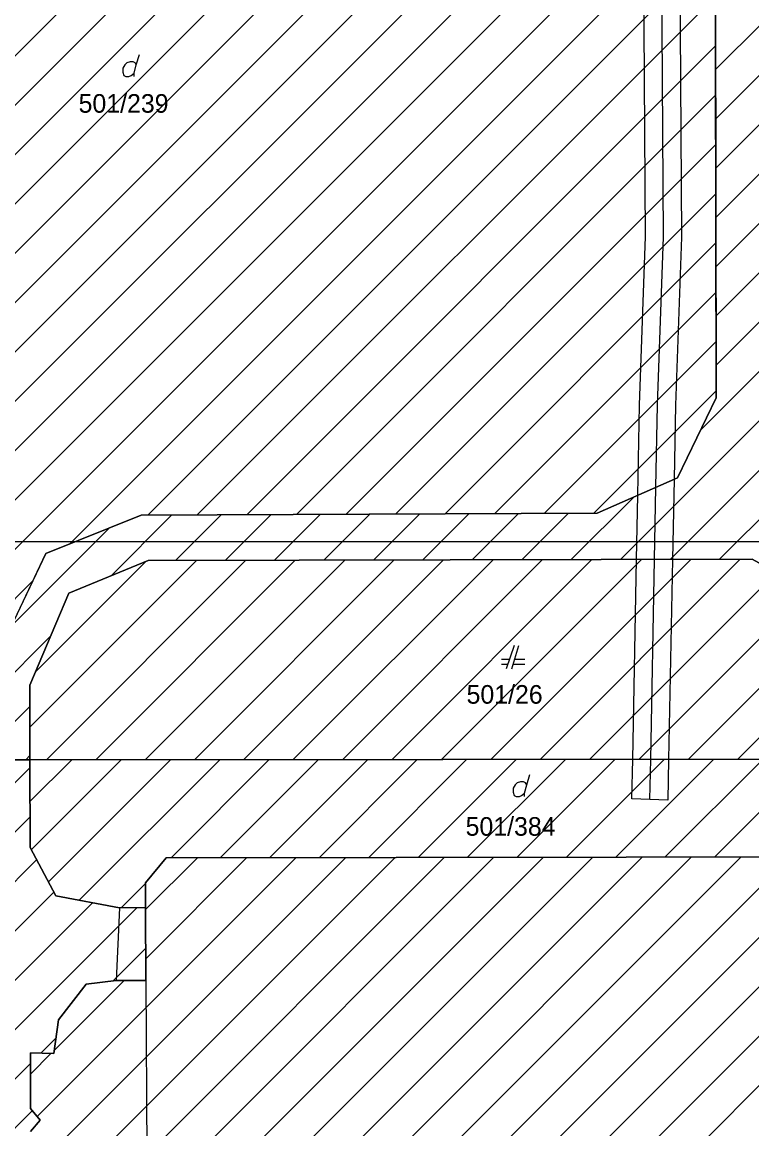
# Model space of a CAD drawing. Extents: x -264309 to -263505, y -1242443 to -1241763.
# Drawn here: x -264073.7 to -264010.9, y -1242101 to -1242005.9 of the extents above; entities that cross this region are included whole.
import ezdxf

# ---------------------------------------------------------------- set-up
doc = ezdxf.new("R2010")
doc.units = 0
for name, color, linetype in [('KN_2019_08_16', 7, 'Continuous'), ('KN_2019_08_16_KLADPAR', 7, 'Continuous'), ('KN_2019_08_16_ZAPPAR', 7, 'Continuous'), ('RAM_NA_TLAC_10xA4_1-500', 7, 'Continuous'), ('SRAFY_PARCELY', 7, 'Continuous')]:
    doc.layers.add(name, color=color, linetype=linetype)

msp = doc.modelspace()

# ---------------------------------------------------------------- linework, layer by layer
at = {"layer": 'KN_2019_08_16'}
msp.add_lwpolyline([(-264014.44, -1241960.47), (-264017.32, -1241970.61), (-264016.97, -1242024.38), (-264017.48, -1242038.84), (-264017.6, -1242045.19), (-264017.74, -1242052.08), (-264018.07, -1242069.28), (-264018.14, -1242072.77), (-264019.68, -1242072.72), (-264021.23, -1242072.66), (-264021.16, -1242069.28), (-264020.83, -1242052.09), (-264020.73, -1242046.57), (-264020.58, -1242038.83), (-264020.07, -1242024.34), (-264020.4, -1241970.09), (-264017.76, -1241960.8), (-264016.1, -1241960.64)], close=True, dxfattribs=at)
msp.add_lwpolyline([(-264019.68, -1242072.72), (-264019.61, -1242069.28), (-264019.28, -1242052.09), (-264019.16, -1242045.88), (-264019.03, -1242038.83), (-264018.52, -1242024.36), (-264018.86, -1241970.35), (-264016.1, -1241960.64)], dxfattribs=at)
at = {"layer": 'KN_2019_08_16_KLADPAR'}
for p, q in [((-264014.12, -1241964.15), (-264013.98, -1242038.21)), ((-264063.85, -1242009.58), (-264063.58, -1242008.68)), ((-264013.98, -1242038.21), (-264017.32, -1242045.06)), ((-264017.32, -1242045.06), (-264024.22, -1242048.12)), ((-264063.42, -1242048.29), (-264071.64, -1242051.59)), ((-264024.22, -1242048.12), (-264063.42, -1242048.29)), ((-264071.64, -1242051.59), (-264076.8, -1242062.43)), ((-264031.35, -1242059.5), (-264032.05, -1242061.5)), ((-264031.55, -1242061.5), (-264030.95, -1242059.5)), ((-264031.77, -1242060.7), (-264032.45, -1242060.7)), ((-264032.45, -1242061.1), (-264031.91, -1242061.1)), ((-264031.43, -1242061.1), (-264030.45, -1242061.1)), ((-264030.45, -1242060.7), (-264031.31, -1242060.7)), ((-264030.28, -1242071.47), (-264030.01, -1242070.57))]:
    msp.add_line(p, q, dxfattribs=at)
for points in [[(-264076.8, -1242062.43), (-264071.64, -1242051.59), (-264063.42, -1242048.29), (-264024.22, -1242048.12), (-264017.32, -1242045.06), (-264013.98, -1242038.21), (-264014.12, -1241964.15)], [(-264064.03, -1242010.57), (-264064.03, -1242010.3), (-264063.85, -1242009.58), (-264063.94, -1242009.4), (-264064.12, -1242009.31), (-264064.39, -1242009.31), (-264064.66, -1242009.4), (-264064.84, -1242009.58), (-264065.02, -1242009.85), (-264065.02, -1242010.21), (-264064.93, -1242010.48), (-264064.75, -1242010.57), (-264064.48, -1242010.57), (-264064.3, -1242010.48), (-264064.03, -1242010.3)], [(-263949.96, -1242070.83), (-263956.24, -1242069.24), (-263956.44, -1242060.64), (-263958.74, -1242055.68), (-263966.57, -1242052.07), (-263989.51, -1242052.11), (-263994.74, -1242054.37), (-263998.21, -1242059.87), (-263998.88, -1242069.26), (-264001.98, -1242069.27), (-264002.01, -1242061.78), (-264004.7, -1242055.47), (-264010.89, -1242052.07), (-264062.83, -1242052.18), (-264069.66, -1242054.98), (-264073.01, -1242062.91), (-264073, -1242069.31), (-264076.82, -1242069.31)], [(-264076.93, -1242111.1), (-264076.9, -1242098.2), (-264076.82, -1242069.31), (-264073, -1242069.31), (-264072.99, -1242076.85), (-264070.77, -1242081.01), (-264065.29, -1242082.03), (-264063.05, -1242082.02), (-264063.02, -1242088.27), (-264065.59, -1242088.27), (-264068.16, -1242088.59), (-264070.53, -1242091.66), (-264070.93, -1242094.55), (-264072.96, -1242094.5), (-264072.96, -1242099.3), (-264072.11, -1242100.28), (-264072.96, -1242101.25)], [(-264030.46, -1242072.46), (-264030.46, -1242072.19), (-264030.28, -1242071.47), (-264030.37, -1242071.29), (-264030.55, -1242071.2), (-264030.82, -1242071.2), (-264031.09, -1242071.29), (-264031.27, -1242071.47), (-264031.45, -1242071.74), (-264031.45, -1242072.1), (-264031.36, -1242072.37), (-264031.18, -1242072.46), (-264030.91, -1242072.46), (-264030.73, -1242072.37), (-264030.46, -1242072.19)], [(-264072.96, -1242101.25), (-264072.11, -1242100.28), (-264072.96, -1242099.3), (-264072.96, -1242094.5), (-264070.93, -1242094.55), (-264070.53, -1242091.66), (-264068.16, -1242088.59), (-264065.59, -1242088.27), (-264063.02, -1242088.27), (-264063.05, -1242082.02), (-264063.06, -1242079.88), (-264061.28, -1242077.73), (-264001.95, -1242077.64), (-264002.01, -1242080.21), (-263996.04, -1242080), (-263982.23, -1242080.21), (-263982.23, -1242081.51), (-263975.78, -1242081.51), (-263975.68, -1242093.61), (-263970.24, -1242093.63), (-263970.22, -1242106.22)]]:
    msp.add_lwpolyline(points, dxfattribs=at)
for points in [[(-264002.01, -1242061.78), (-264001.98, -1242069.27), (-264073, -1242069.31), (-264073.01, -1242062.91), (-264069.66, -1242054.98), (-264062.83, -1242052.18), (-264010.89, -1242052.07), (-264004.7, -1242055.47)], [(-264073, -1242069.31), (-264001.98, -1242069.27), (-264001.95, -1242077.64), (-264061.28, -1242077.73), (-264063.06, -1242079.88), (-264063.05, -1242082.02), (-264065.29, -1242082.03), (-264070.77, -1242081.01), (-264072.99, -1242076.85)]]:
    msp.add_lwpolyline(points, close=True, dxfattribs=at)
at = {"layer": 'KN_2019_08_16_ZAPPAR'}
for p, q in [((-264065.29, -1242082.03), (-264065.59, -1242088.27)), ((-264063.02, -1242088.27), (-264062.89, -1242112.12))]:
    msp.add_line(p, q, dxfattribs=at)
at = {"layer": 'RAM_NA_TLAC_10xA4_1-500'}
msp.add_lwpolyline([(-264210.825, -1242050.537), (-264105.825, -1242050.537), (-264000.825, -1242050.537), (-263895.825, -1242050.537), (-263790.825, -1242050.537), (-263685.825, -1242050.537), (-263685.825, -1242199.037), (-263685.825, -1242347.537), (-263790.825, -1242347.537), (-263895.825, -1242347.537), (-264000.825, -1242347.537), (-264105.825, -1242347.537), (-264210.825, -1242347.537), (-264210.825, -1242199.037)], close=True, dxfattribs=at)
at = {"layer": 'SRAFY_PARCELY'}
for p, q in [((-264101.288, -1242048.528), (-264013.095, -1241960.335)), ((-264104.076, -1242042.83), (-264022.521, -1241961.276)), ((-264102.682, -1242045.679), (-264017.809, -1241960.806)), ((-264105.469, -1242039.982), (-264027.233, -1241961.745)), ((-264099.9, -1242051.383), (-264014.117, -1241965.6)), ((-264098.588, -1242054.313), (-264014.109, -1241969.835)), ((-264097.275, -1242057.243), (-264014.101, -1241974.069)), ((-264095.962, -1242060.173), (-264014.093, -1241978.304)), ((-264094.65, -1242063.103), (-264014.085, -1241982.538)), ((-264093.337, -1242066.033), (-264014.077, -1241986.773)), ((-264092.023, -1242068.962), (-264014.069, -1241991.008)), ((-264069.583, -1242050.764), (-264014.061, -1241995.242)), ((-264062.864, -1242048.288), (-264014.053, -1241999.477)), ((-264058.603, -1242048.269), (-264014.045, -1242003.712)), ((-264014.033, -1242009.986), (-264009.976, -1242005.929)), ((-264054.342, -1242048.251), (-264014.037, -1242007.946)), ((-264014.025, -1242014.22), (-264009.975, -1242010.17)), ((-264050.08, -1242048.232), (-264014.029, -1242012.181)), ((-264014.017, -1242018.455), (-264009.973, -1242014.411)), ((-264045.819, -1242048.214), (-264014.021, -1242016.416)), ((-264014.009, -1242022.69), (-264009.971, -1242018.652)), ((-264041.558, -1242048.195), (-264014.013, -1242020.65)), ((-264014.001, -1242026.924), (-264009.97, -1242022.893)), ((-264037.297, -1242048.177), (-264014.005, -1242024.885)), ((-264013.993, -1242031.159), (-264009.97, -1242027.136)), ((-264033.036, -1242048.158), (-264013.997, -1242029.119)), ((-264013.985, -1242035.394), (-264009.97, -1242031.378)), ((-264028.775, -1242048.14), (-264013.989, -1242033.354)), ((-264015.332, -1242040.983), (-264009.97, -1242035.621)), ((-264024.514, -1242048.121), (-264013.981, -1242037.589)), ((-264022.2, -1242052.094), (-264009.577, -1242039.47)), ((-264017.949, -1242052.085), (-264008.277, -1242042.413)), ((-264013.697, -1242052.076), (-264006.739, -1242045.118)), ((-264026.452, -1242052.103), (-264021.074, -1242046.725)), ((-264066.021, -1242053.488), (-264060.812, -1242048.279)), ((-264060.465, -1242052.175), (-264056.55, -1242048.26)), ((-264056.214, -1242052.166), (-264052.289, -1242048.242)), ((-264051.962, -1242052.157), (-264048.028, -1242048.223)), ((-264047.71, -1242052.148), (-264043.767, -1242048.205)), ((-264043.459, -1242052.139), (-264039.506, -1242048.186)), ((-264039.207, -1242052.13), (-264035.245, -1242048.168)), ((-264034.955, -1242052.121), (-264030.984, -1242048.149)), ((-264030.704, -1242052.112), (-264026.723, -1242048.131)), ((-264074.615, -1242057.839), (-264066.169, -1242049.394)), ((-264073.004, -1242066.498), (-264058.677, -1242052.171)), ((-264072.536, -1242061.787), (-264062.997, -1242052.248)), ((-264071.572, -1242069.309), (-264054.425, -1242052.162)), ((-264067.327, -1242069.307), (-264050.174, -1242052.153)), ((-264063.082, -1242069.304), (-264045.922, -1242052.144)), ((-264058.837, -1242069.302), (-264041.671, -1242052.135)), ((-264054.592, -1242069.3), (-264037.419, -1242052.126)), ((-264050.347, -1242069.297), (-264033.167, -1242052.117)), ((-264046.102, -1242069.295), (-264028.916, -1242052.108)), ((-264041.857, -1242069.292), (-264024.664, -1242052.099)), ((-264037.612, -1242069.29), (-264020.412, -1242052.09)), ((-264033.367, -1242069.288), (-264016.161, -1242052.081)), ((-264029.122, -1242069.285), (-264011.909, -1242052.072)), ((-264024.877, -1242069.283), (-264008.808, -1242053.214)), ((-264090.674, -1242071.855), (-264072.758, -1242053.94)), ((-264020.632, -1242069.281), (-264006.069, -1242054.718)), ((-264016.387, -1242069.278), (-264004.066, -1242056.957)), ((-264076.805, -1242064.273), (-264071.231, -1242058.698)), ((-264012.142, -1242069.276), (-264002.798, -1242059.932)), ((-264076.818, -1242068.528), (-264073.007, -1242064.717)), ((-264073.358, -1242069.31), (-264073.001, -1242068.953)), ((-264072.995, -1242072.903), (-264069.4, -1242069.308)), ((-264072.889, -1242077.04), (-264065.155, -1242069.306)), ((-264071.413, -1242079.806), (-264060.91, -1242069.303)), ((-264068.75, -1242081.386), (-264056.665, -1242069.301)), ((-264060.851, -1242077.729), (-264052.42, -1242069.298)), ((-264056.602, -1242077.723), (-264048.175, -1242069.296)), ((-264052.353, -1242077.716), (-264043.93, -1242069.294)), ((-264048.103, -1242077.71), (-264039.685, -1242069.291)), ((-264043.854, -1242077.704), (-264035.44, -1242069.289)), ((-264039.605, -1242077.697), (-264031.195, -1242069.286)), ((-264035.356, -1242077.691), (-264026.95, -1242069.284)), ((-264031.107, -1242077.684), (-264022.705, -1242069.282)), ((-264026.858, -1242077.678), (-264018.46, -1242069.279)), ((-264022.609, -1242077.671), (-264014.215, -1242069.277)), ((-264018.36, -1242077.665), (-264009.969, -1242069.274)), ((-264014.111, -1242077.658), (-264005.724, -1242069.272)), ((-264076.833, -1242073.836), (-264072.999, -1242070.003)), ((-264076.844, -1242078.091), (-264072.993, -1242074.24)), ((-264076.856, -1242082.345), (-264072.423, -1242077.912)), ((-264072.96, -1242104.826), (-264045.841, -1242077.707)), ((-264072.364, -1242099.987), (-264050.09, -1242077.713)), ((-264070.699, -1242106.808), (-264041.592, -1242077.7)), ((-264069.632, -1242109.983), (-264037.342, -1242077.694)), ((-264067.119, -1242111.713), (-264033.093, -1242077.687)), ((-264063.285, -1242112.121), (-264028.844, -1242077.681)), ((-264063.049, -1242082.187), (-264058.588, -1242077.726)), ((-264063.029, -1242086.41), (-264054.339, -1242077.719)), ((-264062.884, -1242115.963), (-264024.595, -1242077.674)), ((-264062.88, -1242120.202), (-264020.346, -1242077.668)), ((-264060.935, -1242122.5), (-264016.097, -1242077.661)), ((-264056.691, -1242122.498), (-264011.848, -1242077.655)), ((-264052.446, -1242122.496), (-264007.599, -1242077.649)), ((-264048.202, -1242122.494), (-264003.35, -1242077.642)), ((-264065.151, -1242082.029), (-264063.06, -1242079.938)), ((-264043.957, -1242122.492), (-264001.663, -1242080.198)), ((-264039.713, -1242122.49), (-263997.265, -1242080.043)), ((-264035.468, -1242122.489), (-263993.026, -1242080.046)), ((-264076.868, -1242086.599), (-264070.947, -1242080.678)), ((-264076.891, -1242095.108), (-264063.807, -1242082.023)), ((-264076.88, -1242090.854), (-264067.622, -1242081.596)), ((-264065.842, -1242088.301), (-264063.033, -1242085.493)), ((-264070.892, -1242094.272), (-264064.889, -1242088.27)), ((-264072.063, -1242094.522), (-264070.744, -1242093.203)), ((-264072.96, -1242096.341), (-264071.164, -1242094.544)), ((-264076.903, -1242099.362), (-264072.96, -1242095.419)), ((-264076.913, -1242103.615), (-264072.792, -1242099.494))]:
    msp.add_line(p, q, dxfattribs=at)

# ---------------------------------------------------------------- texts
at = {"layer": 'KN_2019_08_16_KLADPAR'}
for s, p in [('501/239', (-264068.811, -1242013.69)), ('501/26', (-264035.449, -1242064.49)), ('501/384', (-264035.531, -1242075.84))]:
    msp.add_text(s, height=1.6, dxfattribs=at).set_placement(p)

doc.saveas('drawing.dxf')
